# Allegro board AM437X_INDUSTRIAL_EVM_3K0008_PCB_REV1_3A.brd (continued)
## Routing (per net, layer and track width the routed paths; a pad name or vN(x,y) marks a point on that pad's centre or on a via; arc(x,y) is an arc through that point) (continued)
SPI0_DIN: length 106.3
  TOP w0.13: v1(84.53,80.85) 84.53,78.71 83.43,77.61 83.43,73.55 83.2,73.32 82.75,73.32 U11.T22
  L4_SIG2 w0.13: J16.26 102.37,4.82 102.37,6.61 105.95,10.2 106.62,10.2 107.21,10.78 107.21,14.68 107.61,15.08 107.61,20.92 108.65,21.96 108.65,24.44 108.65,24.44 108.65,24.95 109.76,26.06 109.76,29.87 107.78,31.85 107.78,35.98 107.47,36.29 107.47,39.61 108.47,40.61 108.47,44.41 109.66,45.6 109.66,48.3 108.75,49.22 108.75,52.8 105.26,56.28 103.58,56.28 101.62,58.25 101.62,59.62 101.3,59.94 97.19,64.04 97.19,64.88 96.76,65.32 94.99,67.08 94.99,72.81 92.37,75.43 92.37,78.55 90.71,80.21 85.64,80.21 85,80.85 v1(84.53,80.85)
SPI0_SCLK: length 103.4
  L4_SIG2 w0.13: J16.24 106.37,4.86 106.37,6.29 109.35,9.27 109.35,11.48 108.75,12.08 108.75,14.04 109.15,14.44 109.15,20.28 110.19,21.32 110.19,24.31 110.59,24.71 111.3,25.42 111.3,29.88 111.3,36.03 111.01,36.33 111.01,38.38 111.83,39.19 111.83,45.02 111.35,45.49 111.35,48.79 110.36,49.79 110.36,53.55 107.7,56.21 107.7,58.61 107.44,58.87 106.96,58.87 102.99,62.84 102.22,63.61 99.81,63.61 98.73,64.68 98.73,66.64 97.72,67.66 97.72,68.98 96.71,69.99 96.71,75.54 91.79,80.46 91.79,80.47 91.43,80.83 87.83,80.83 86.49,82.17 84.36,82.17 84.02,81.82 83.62,81.82 82.3,83.15 v1(82.3,84.84)
  BOTTOM w0.13: v1(82.3,84.84) 82.3,84.2 R385.2
SPIMEM_CLK: length 40.9
  TOP w0.13: R128.1 63.34,67.15 60.11,67.15 59.56,67.69 57.58,67.69 56.94,67.06 56.24,67.06 55.68,67.62 47.42,67.62 46.15,68.89 43.81,68.89 43.59,69.11 43.59,69.41 43.74,69.56 45.21,69.56 45.38,69.73 45.38,70.01 45,70.38 45,70.39 44.49,70.9 42.96,70.9 42.16,70.1 42.16,68.96 v1(42.93,68.2)
  BOTTOM w0.13: U46.16 44.45,60.83 43.43,61.85 43.43,67.69 v1(42.93,68.2)
SPIMEM_CS: length 35.3
  TOP w0.13: v1(41.53,68.83) 45.3,65.06 46.95,65.06 49.53,62.48 49.53,62.46 50.04,61.96 50.5,61.96 50.65,62.11 50.65,62.28 50.8,62.43 51.02,62.43 51.17,62.28 51.17,62.11 51.32,61.96 51.54,61.96 51.69,62.11 51.69,62.28 51.85,62.43 52.06,62.43 52.21,62.28 52.21,62.11 52.37,61.96 52.58,61.96 52.73,62.11 52.73,62.28 52.89,62.43 53.1,62.43 53.26,62.28 53.26,62.11 53.41,61.96 53.62,61.96 53.78,62.11 53.78,62.28 53.93,62.43 54.15,62.43 54.3,62.28 54.3,62.11 54.45,61.96 55.39,61.96 55.54,62.11 55.54,62.74 55.7,62.89 55.91,62.89 56.06,62.74 56.06,62.11 56.22,61.96 56.43,61.96 56.59,62.11 56.59,62.74 56.74,62.89 56.95,62.89 57.11,62.74 57.11,62.11 57.26,61.96 57.42,61.96 58.6,63.14 60.2,63.14 60.73,62.61 61.85,62.61 62.86,61.59 R144.1
  BOTTOM w0.13: v1(41.53,68.83) 41.15,68.45 U46.7
SPIMEM_D0: length 31.8
  TOP w0.13: v1(44.58,66.82) 46.13,66.82 46.66,66.29 48.62,66.29 49.28,65.63 49.96,65.63 50.6,66.27 54.76,66.27 55.47,65.56 55.47,64.28 55.86,63.88 56.03,63.88 56.19,64.03 56.19,64.55 56.34,64.7 56.55,64.7 56.71,64.55 56.71,64.03 56.86,63.88 57.66,63.88 58.17,64.39 R137.1
  BOTTOM w0.13: v1(44.58,66.82) 44.23,66.47 44.23,66.13 44.38,65.98 45.08,65.98 45.23,65.83 45.23,65.61 45.08,65.46 44.38,65.46 44.23,65.3 44.23,65.09 44.38,64.94 45.08,64.94 45.23,64.78 45.23,64.57 45.08,64.41 44.38,64.41 44.23,64.26 44.23,64.05 44.38,63.89 45.08,63.89 45.23,63.74 45.23,63.52 45.08,63.37 44.38,63.37 44.23,63.22 44.23,62.87 44.99,62.1 U46.15
SPIMEM_D1: length 29.5
  TOP w0.13: v1(42.93,70.1) 42.93,68.96 43.43,68.45 45.97,68.45 47.24,67.18 55.5,67.18 56.06,66.62 57.12,66.62 57.76,67.26 59.36,67.26 59.94,66.67 v1(61.34,66.67)
  BOTTOM w0.13: R449.1 v1(61.34,66.67) ; v1(42.93,70.1) 41.21,70.1 41.05,69.95 41.05,69.62 40.9,69.47 40.69,69.47 40.53,69.62 40.53,69.95 40.38,70.1 39.75,70.1 39.37,69.72 U46.8
SPIMEM_D2: length 28.6
  TOP w0.13: v1(58.93,63.63) 58.04,63.63 57.78,63.37 55.35,63.37 54.89,62.92 49.71,62.92 48.82,63.81 48.82,65.48 48.46,65.84 46.18,65.84 v1(45.72,66.29)
  BOTTOM w0.13: v1(45.72,66.29) 45.09,66.93 45.09,68.49 44.88,68.69 44.28,68.69 44.12,68.86 44.12,69.5 44.34,69.72 U46.9 ; R457.1 59.94,64.39 59.25,64.39 58.93,64.06 v1(58.93,63.63)
SPIMEM_D3: length 34.6
  TOP w0.13: v1(44.45,67.82) 45.01,67.25 46.44,67.25 46.94,66.75 55.32,66.75 55.9,66.17 55.9,65.81 56.25,65.46 60.13,65.46 60.2,65.53 v1(60.32,65.53)
  BOTTOM w0.13: v1(60.32,65.53) 60.5,65.53 60.86,65.18 61.38,65.18 61.58,65.38 61.9,65.38 62.1,65.18 62.42,65.18 62.78,65.53 R453.1 ; U46.1 39.01,60.83 39.28,60.56 40.37,60.56 41.06,61.25 41.06,62.17 42.45,63.57 42.45,68.39 42.73,68.67 43.6,68.67 v1(44.45,67.82)
SYNCI: length 96
  TOP w0.13: v1(111.25,10.16) R257.1 ; v1(82.8,80.7) 82.8,78.99 82.04,78.23 82.04,75.72 81.48,75.16 81.48,74.61 U11.R24
  L4_SIG2 w0.13: v1(106.43,13.72) 105.76,13.72 105.3,14.17 105.3,18.87 106.12,19.68 106.12,21.53 107.16,22.58 107.16,23.82 107.16,25.57 108.27,26.68 108.27,29.18 106.29,31.16 106.29,35.3 105.98,35.61 105.98,36.97 105.98,40.23 106.33,40.57 106.33,44.16 105.48,45.01 105.48,49.95 102.22,53.21 101.06,54.37 101.06,56.54 100.13,57.48 100.13,59.01 99.81,59.32 95.71,63.43 95.71,64.27 93.51,66.47 93.51,70.78 90.04,74.24 90.04,75.22 88.35,76.92 88.35,77.64 87.12,78.87 83.82,78.87 82.8,79.88 v1(82.8,80.7)
  BOTTOM w0.13: v1(111.25,10.16) 107.7,13.72 v1(106.43,13.72)
SYS_RESETN: length 386.6
  TOP w0.13: R152.2 v1(37.08,57.15) ; v1(15.49,73.79) 19.3,77.6 v1(22.23,77.6) ; v1(45.69,116.05) 46.48,116.84 48,116.84 48,116.84 54.11,116.84 54.93,116.01 58.08,116.01 58.09,116.02 59.33,116.02 61.97,118.66 136.1,118.66 138.3,116.46 138.3,98.76 133.01,93.46 133.01,83.78 v1(133.48,83.31)
  L3_SIG1 w0.13: v1(129.29,36.58) 130.3,37.59 130.3,45.47 134.87,50.04 134.87,50.93 135.64,51.69 v1(135.64,52.45) ; v1(24.89,105.41) 24.97,105.41 27.82,108.26 31.38,108.26 34.85,111.73 34.85,116.79 36.69,118.63 43.35,118.63 44.83,117.15 44.83,116.92 v1(45.69,116.05) ; v1(133.48,83.31) 134.75,82.04 v1(134.75,73.53)
  L4_SIG2 w0.13: v1(135.64,52.45) 135.64,69.41 134.75,70.3 v1(134.75,73.53) ; v1(37.08,57.15) 37.74,57.81 37.74,58.9 36.37,60.27 33.6,60.27 29.88,56.55 19.16,56.55 17.87,57.84 17.87,58.31 18.41,58.86 18.41,70.87 v1(15.49,73.79) 15.49,74.36 13.91,75.95 13.91,86.17 14.59,86.85 14.59,101.71 16.51,103.63 18.34,103.63 20.31,105.6 23.73,105.6 23.92,105.41 v1(24.89,105.41)
  BOTTOM w0.13: U43.2 v1(22.23,77.6) 26.8,77.6 28.19,78.99 28.19,83.57 28.56,83.94 30.1,83.94 30.47,83.57 30.47,83.05 30.35,82.94 U42.2 ; R389.2 v1(133.48,83.31) ; J16.25 104.33,4.86 104.33,3.32 105.01,2.63 123.72,2.63 124.37,3.29 124.37,7.48 125.35,8.46 125.35,11.38 122.63,14.1 122.63,28.22 129.29,34.87 v1(129.29,36.58) R499.1 ; U44.2 v1(15.49,73.79)
SYS_WARMRESETN: length 153.2
  TOP w0.13: R86.2 75.56,84.58 v1(75.56,86.87) 76.07,86.87 R69.1
  L3_SIG1 w0.13: v1(135.5,73.15) 135.5,73.53 135.5,73.54 135.5,84.84 134.34,86 134.34,86.84 134.09,87.08 134.09,87.95 135.01,88.87 135.01,95.56 135.72,96.27 135.72,98.03 131.21,102.54 129.51,102.54 127.14,104.91 111.57,104.91 111,105.48 107.78,105.48 106.81,104.51 101.18,104.51 98.09,101.42 94.56,101.42 91.8,98.65 83.21,98.65 79.61,95.06 79.61,92.05 76.53,88.97 76.09,88.97 75.56,88.44 v1(75.56,86.87) ; v1(136.14,51.31) 136.14,48.01 135.14,47 v1(135.14,41.42) 133.99,40.26 v1(131.95,40.26)
  L4_SIG2 w0.13: v1(135.5,73.15) 135.5,73.14 135.06,72.7 135.06,70.42 136.02,69.46 136.02,53 136.14,52.87 v1(136.14,51.31)
  BOTTOM w0.13: U54.4 v1(135.14,41.42) ; R499.2 R498.1 C287.1 v1(131.95,40.26) 129.03,40.26 127.64,41.66 R489.1
SYSBOOT0: length 22
  TOP w0.13: R26.1 v1(62.1,98.37) 62.1,97.54 61.72,97.16 61.72,94.63 59.85,92.76 59.85,85.67 60.03,85.5 60.03,82.03 59.32,81.32 U9.17
  BOTTOM w0.13: R26.1 v1(62.1,98.37)
SYSBOOT1: length 20.1
  TOP w0.13: U9.15 59.22,82.62 59.72,83.12 59.72,85.37 59.54,85.54 59.54,93.58 60.45,94.49 60.45,98.04 60.71,98.3 v1(60.71,98.37) R25.1
  BOTTOM w0.13: R25.1 v1(60.71,98.37)
SYSBOOT2: length 18.3
  TOP w0.13: U9.13 59.05,83.92 59.4,84.27 59.4,85.25 59.24,85.42 59.24,94.31 58.93,94.61 58.93,97.92 59.31,98.3 v1(59.31,98.35) R24.1
  BOTTOM w0.13: R24.1 v1(59.31,98.35)
SYSBOOT3: length 16.6
  TOP w0.13: R23.1 57.91,98.48 v1(57.64,98.22) 57.66,98.2 57.66,93.6 58.93,92.33 58.93,86.44 57.71,85.22 U9.11
  BOTTOM w0.13: R23.1 57.91,98.48 v1(57.64,98.22)
SYSBOOT4: length 20.8
  TOP w0.13: R30.1 v1(67.69,98.35) ; v1(64.16,83.92) U9.8
  L3_SIG1 w0.13: v1(64.16,83.92) 64.88,84.64 64.88,85.48 64.6,85.76 64.36,86 63.95,86 62.79,87.16 62.79,92.8 66.43,96.44 66.43,97.36 67.17,98.09 67.44,98.09 v1(67.69,98.35)
  BOTTOM w0.13: R30.1 v1(67.69,98.35)
SYSBOOT5: length 23.4
  TOP w0.13: U9.6 61.52,82.62 60.95,83.2 60.95,85.88 60.78,86.06 60.78,92.38 61.72,93.32 65.38,93.32 66.29,94.24 v1(66.29,98.37) R29.1
  BOTTOM w0.13: R29.1 v1(66.29,98.37)
SYSBOOT6: length 23.4
  TOP w0.13: U9.4 61.68,81.32 60.64,82.36 60.64,85.75 60.47,85.93 60.47,92.5 61.59,93.63 63.62,93.63 64.9,94.91 v1(64.9,98.37) R28.1
  BOTTOM w0.13: R28.1 v1(64.9,98.37)
SYSBOOT7: length 23.8
  TOP w0.13: R27.1 v1(63.5,98.37) 63.5,97.54 63.12,97.16 63.12,94.53 62.53,93.94 61.46,93.94 60.16,92.63 60.16,85.8 60.33,85.63 60.33,81.34 61.66,80.02 U9.2
  BOTTOM w0.13: R27.1 v1(63.5,98.37)
SYSBOOT8: length 10.9
  TOP w0.13: R39.1 v1(62.48,94.49)
  BOTTOM w0.13: U39.17 61.97,88.81 61.92,88.86 60.87,88.86 60.45,89.28 60.45,93.29 61.65,94.49 v1(62.48,94.49) R39.1
SYSBOOT9: length 9.5
  TOP w0.13: R40.1 v1(63.88,94.49)
  BOTTOM w0.13: U39.15 61.9,90.11 60.94,91.07 60.94,92.95 61.85,93.85 63.25,93.85 v1(63.88,94.49) R40.1
SYSBOOT10: length 9.3
  TOP w0.13: R41.1 v1(65.53,94.49)
  BOTTOM w0.13: U39.13 61.53,91.41 61.25,91.69 61.25,92.3 62.08,93.13 63.56,93.13 64.91,94.49 v1(65.53,94.49) R41.1
SYSBOOT11: length 6.3
  TOP w0.13: R42.1 v1(66.93,94.49)
  BOTTOM w0.13: U39.11 63.58,92.71 64.78,93.92 66.36,93.92 v1(66.93,94.49) R42.1
SYSBOOT12: length 7.5
  TOP w0.13: R35.1 v1(56.9,94.49)
  BOTTOM w0.13: R35.1 v1(56.9,94.49) 56.9,93.85 57.39,93.36 58.16,93.36 58.89,92.62 58.89,91.87 58.44,91.41 U39.8
SYSBOOT13: length 7.8
  TOP w0.13: R36.1 v1(58.29,94.49)
  BOTTOM w0.13: U39.6 58.11,90.11 59.2,91.2 59.2,92.95 58.29,93.85 v1(58.29,94.49) R36.1
SYSBOOT14: length 9.3
  TOP w0.13: R37.1 v1(59.69,94.49)
  BOTTOM w0.13: R37.1 v1(59.69,94.49) 59.69,93.85 59.51,93.67 59.51,89.48 58.84,88.81 U39.4
SYSBOOT15: length 11.1
  TOP w0.13: R38.1 v1(61.09,94.59)
  BOTTOM w0.13: U39.2 58.81,87.51 59.82,88.52 59.82,93.32 v1(61.09,94.59) R38.1
TCK: length 3
  TOP w0.13: J7.11 v1(137.67,80.77)
  BOTTOM w0.13: v1(137.67,80.77) R407.1
UARTX_RXD: length 51.2
  TOP w0.13: R89.2 80.67,84.1 80.67,85.06 80.38,85.35 v1(80.38,86.61) ; U13.38 112.35,62.21 113.03,62.89 113.03,63.88 v1(112.67,64.24)
  L4_SIG2 w0.13: v1(80.38,86.61) 80.82,87.05 81.74,87.05 82.52,87.83 84.13,87.83 86.28,85.68 86.56,85.68 86.96,85.28 91.2,85.28 96.05,80.42 96.69,80.42 98.51,78.59 99.55,78.59 100.2,77.94 100.2,75.15 100.75,74.6 100.75,73.29 104.81,69.23 104.81,68.73 105.32,68.22 106.73,68.22 108.41,66.55 110.25,66.55 112.56,64.24 v1(112.67,64.24)
UARTX_TXD: length 54.6
  TOP w0.13: v1(109.22,69.72) 109.22,65.76 108.81,65.35 108.81,62.46 109.56,61.71 U13.39 ; R88.2 79.2,84.53 79.2,85.49 78.74,85.95 v1(78.74,86.61)
  L4_SIG2 w0.13: v1(109.22,69.72) 108.53,70.41 105.37,70.41 100.51,75.28 100.51,78.07 99.68,78.9 98.64,78.9 96.81,80.73 96.18,80.73 93.28,83.63 93.28,85.07 92.5,85.85 91.06,85.85 90.42,86.49 87.76,86.49 87.51,86.73 86.11,86.73 84.71,88.14 82.39,88.14 81.61,87.36 79.48,87.36 v1(78.74,86.61)
USBJTAG_ENN: length 54.4
  L4_SIG2 w0.13: v1(134.49,48.13) 134.68,48.32 134.68,50.2 133.86,51.03 133.86,53.21 134.73,54.08 134.73,58.4 133.48,59.65 133.48,63.3 130.81,65.96 130.81,68.45 129.16,70.1 v1(128.37,70.1)
  BOTTOM w0.13: U45.14 127.72,75.48 R421.2 ; U45.15 v1(128.37,70.1) 129.18,70.1 129.63,70.55 130.74,70.55 132.97,72.77 132.97,76.07 131.83,77.22 131.83,80.26 132.91,81.35 132.91,82.36 131.92,83.35 U41.4 ; v1(134.49,48.13) 133.06,49.57 U49.4
VADD33_PRUETH0: length 3.4
  TOP w0.305: U7.14 24.11,90.53 23.88,90.3 23.37,90.3 23.24,90.42 C33.1
  TOP w0.508: C33.1 v3(22.61,89.67)
VADD33_PRUETH1: length 3.4
  TOP w0.305: C58.1 23.24,65.15 23.37,65.02 23.88,65.02 24.11,65.26 U12.14
  TOP w0.508: C58.1 v3(22.61,64.4)
VAM437X_DDR_VREF: length 0.5
  TOP w0.13: U11.T6 82.48,62.6 v1(82.81,62.93)
VENDAT: length 7
  BOTTOM w0.508: 10.8,38.02 J10.8 ; J10.8 10.8,39.66 ; J10.8 12.44,39.66 ; J10.8 12.44,38.02 ; 13.02,35.33 J10.2 11.37,35.33
VETH1_AVDDH: length 7.3
  BOTTOM w0.254: v3(39.88,97.16) 40.43,96.6 U37.1 ; v3(38.86,95.25) 39.15,94.96 U37.47 ; U37.12 45.93,96.48 46.35,96.9 C142.1
  BOTTOM w0.508: v3(39.48,78.99) C182.1 v3(40.64,80.26) ; C142.1 v3(47.12,97.92)
  vias: v3(36.32,72.77) v3(39.62,72.39) v3(40.26,71.5) v3(40.89,72.39)
VETH1_AVDDL: length 9
  TOP w0.508: v3(52.47,99.69) FB2.2 v3(51.45,98.68) ; v3(51.18,99.95) 50.53,99.95 C21.1 v3(50.02,100.71)
  BOTTOM w0.254: U37.4 41.93,97.06 41.68,97.31 v3(41.68,97.74) ; U37.9 44.43,97.01 44.83,97.41 C143.1
  BOTTOM w0.508: C143.1 v3(44.07,97.92)
VETH1_AVDDL_PLL: length 8.2
  TOP w0.508: v3(52.47,95.63) FB3.2 v3(51.43,96.65) ; C26.1 v3(37.85,93.98) ; v3(35.69,95.65) C22.1 37.32,96.01 v3(38.23,96.01)
  BOTTOM w0.254: C26.1 37.86,93.22 38.1,93.46 U37.44
  BOTTOM w0.508: C26.1 v3(37.85,93.98)
VETH1_AVDDL_PMOS: length 6.1
  TOP w0.508: v3(54.47,94.87) FB4.1 v3(54.47,92.84) ; v3(55.5,98.68) FB2.1 v3(54.47,97.66) ; v3(54.47,95.63) FB3.1 v3(55.5,96.65)
  vias: v3(33.78,76.33) v3(33.78,75.06) v3(35.05,76.33) v3(35.05,75.06)
VETH1_DVDDH: length 33.8
  TOP w0.508: v3(37.34,81.67) 37.21,81.55 37.21,79.88 34.81,77.48 v3(29.72,77.48) ; R66.2 v3(37.59,87.76)
  BOTTOM w0.254: v3(37.34,91.19) 37.61,91.46 U37.40 ; v3(41.02,88.01) 41.43,88.42 U37.34 ; C149.1 48.77,94.61 48.11,93.96 U37.16
  BOTTOM w0.381: v3(29.72,77.48) C187.1 29.72,80.13 U42.5
  BOTTOM w0.508: v3(34.52,82.91) 33.82,82.91 R401.1 34.13,83.79 v3(34.59,83.79) ; R336.1 v3(51.18,95.63) ; v3(41.91,81.67) R396.1 R395.1 ; R345.1 v3(51.18,92.84) ; v3(37.34,81.67) R400.1 R399.1 ; v3(46.48,81.67) R392.1 R393.1 ; D20.1 v3(33.27,85.34) ; 31.12,85.72 v3(32,85.72) ; v3(49.17,93.83) 49.28,93.93 C149.1 ; R353.2 v3(36.58,90.42)
VETH1_DVDDL: length 16.9
  L3_SIG1 w0.508: v3(43.81,87.88) 42.16,89.53 39.37,89.53 v3(38.23,90.68)
  BOTTOM w0.254: U37.23 49.24,90.46 C162.1 ; U37.30 43.43,88.27 v3(43.81,87.88) ; U37.39 38.56,90.96 38.28,90.68 v3(38.23,90.68) ; v3(47.57,92.85) 47.47,92.96 U37.18 ; U37.14 v3(47.75,94.96) ; v3(45.97,87.88) 45.43,88.43 U37.26
  BOTTOM w0.508: C162.1 v3(49.28,89.66)
VMTR_PWRIN: length 4.6
  TOP w0.508: 3.39,17.53 J14.1 ; J14.1 3.39,19.14 ; J14.1 5,19.14 ; J14.1 5,17.53
VPWRIN_JCK: length 13.7
  TOP w0.508: J12.1 127.14,21.25 ; J12.1 127.14,24.47 ; J12.1 123.91,21.25 ; J12.1 123.91,24.47 ; 135.19,19.64 J13.1 ; J13.1 136.81,19.64 ; J13.1 136.81,21.25 ; J13.1 135.19,21.25
VUSB_FTDI: length 27.4
  TOP w0.254: R168.2 v1(114.18,51.69)
  TOP w0.508: D12.2 132.27,67.1 v1(131.47,67.89)
  L4_SIG2 w0.508: v3(127.89,62) 128.14,62.26 128.14,63.37 128.83,64.06 128.83,66.28 v3(130.24,67.69)
  BOTTOM w0.508: v1(114.18,51.69) 114.89,52.4 116.79,52.4 122.55,58.17 122.55,59.31 125.25,62 v3(127.89,62)
VUSB_JTAG: length 4.9
  TOP w0.508: v3(133.6,64.39) 133.6,62.23 132.46,61.09 v3(132.45,61.09)
  BOTTOM w0.305: U47.1 v3(132.45,61.09)
XTIN: length 13.2
  TOP w0.13: U13.2 124.53,57.71 125.86,56.39 v1(130.3,56.39)
  BOTTOM w0.13: v1(130.3,56.39) 130.05,56.13 130.05,55.5 129.79,55.24 C261.1 128.02,55.24 126.73,53.96 Y4.1
XTOUT: length 12.2
  TOP w0.13: U13.3 125.18,58.21 126.24,57.15 v1(130.18,57.15)
  BOTTOM w0.13: v1(130.18,57.15) 129.67,56.64 C255.1 128.02,56.64 126.6,58.06 Y4.2
N10692191: length 9.3
  TOP w0.13: SW2.3 SW2.4 131.14,37.72 v1(129.29,37.72)
  BOTTOM w0.13: R498.2 v1(129.29,37.72)
N11217419: length 2
  BOTTOM w0.13: R508.1 R507.1 C306.1
N11219802: length 1.5
  TOP w0.305: R232.1 93.35,11.82 U25.7
N11219922: length 1.5
  TOP w0.305: R233.1 93.98,11.48 94.35,11.85 U25.9
N11219986: length 2.9
  TOP w0.254: U25.5 92.75,15.75 C108.1 R225.1
N11220684: length 2.7
  TOP w0.254: C109.1 96.55,15.85 U25.1
  BOTTOM w0.508: R549.2 96.77,16.13 v1(97.03,16.38)
N11290828: length 8.8
  TOP w0.13: R87.1 76.95,82.92 76.95,81.92 76.67,81.64 76.67,78.6 77.22,78.05 77.22,77.52 76.94,77.24 76.94,75.81 76.59,75.46 U11.G25
N11290910: length 11.1
  TOP w0.13: U11.G22 76.34,73 76.24,73.1 76.24,73.52 76.24,73.52 76.24,75.44 76.71,75.91 76.71,76.61 76.17,77.14 76.17,81.44 75.69,81.93 75.69,82.68 R86.1
N11291034: length 10.7
  TOP w0.13: R90.1 85.6,81.25 84.78,80.44 84.78,78.56 84.04,77.82 84.04,74.21 84.26,73.99 84.69,73.99 U11.Y23
N12081710: length 23.5
  BOTTOM w0.13: J8.1 30.86,77.6 32.79,77.6 34.54,79.35 34.54,80.23 36.48,82.16 36.48,84.3 36.63,84.45 36.63,86.62 35.81,87.43 35.81,88.66 36.32,89.16 37.06,89.16 37.56,89.66 R353.1 38.23,89.66 39.03,90.46 U37.38
N12123192: length 7
  BOTTOM w0.13: R270.2 33.77,115.56 J4.11
N12123204: length 7.3
  BOTTOM w0.13: J4.14 41.41,116.08 38.23,116.08 R269.2
N12138943: length 2.2
  TOP w0.13: v1(39.12,96.52) 39.12,96.9 R32.1
  BOTTOM w0.13: U37.48 39.71,95.93 v1(39.12,96.52)
N12139138: length 10.4
  BOTTOM w0.13: TP18.1 35.94,86.87 35.43,87.38 35.43,89.99 35.87,90.42 35.87,90.81 36.88,91.82 38.61,91.82 38.75,91.96 U37.41
N12220066: length 11.7
  TOP w0.305: U7.24 29.94,88.81 v3(31.12,87.63) C38.1 ; U7.13 v1(23.88,91.03) ; v1(23.46,88.67) 23.49,88.7 23.49,89.15 24.37,90.03 U7.15
  BOTTOM w0.508: v1(23.88,91.03) 24.64,90.27 C163.1 C164.1 ; v1(23.46,88.67) 23.3,88.5 C167.1 v3(20.95,88.5)
N12225140: length 4.4
  BOTTOM w0.13: J9.11 4.32,73.93 R420.1
N12225158: length 11.8
  TOP w0.305: U12.15 24.37,64.76 23.51,63.89 v1(23.51,63.25) ; U12.13 v1(23.88,65.76) ; C65.1 v3(31.12,62.23) 29.81,63.53 U12.24
  BOTTOM w0.508: C237.1 C232.1 24.64,65 v1(23.88,65.76) ; v3(20.9,63.23) C244.1 23.49,63.23 v1(23.51,63.25)
N12225278: length 44.1
  TOP w0.13: v1(35.69,66.27) 34.54,66.27 33.93,65.66 R134.1 ; J9.10 5.1,57.66 11.97,57.66 13.04,58.74 16.29,58.74 16.99,58.04 v1(18.34,58.04)
  L4_SIG2 w0.13: v1(18.34,58.04) 18.88,57.49 30.32,57.49 33.63,60.81 33.63,65.91 33.99,66.27 v1(35.69,66.27)
N12225708: length 9.9
  TOP w0.13: v1(66.04,57.15) 68.83,59.94 69.4,59.94 70.39,60.92 72.3,60.92 72.57,60.65 U11.A3
  BOTTOM w0.13: R473.2 65.53,56.64 v1(66.04,57.15)
N12225872: length 9.8
  TOP w0.13: U11.E24 75.63,74.64 75.63,75.16 76.43,75.96 76.43,76.56 75.84,77.14 75.84,81.34 75.06,82.13 R85.2
N12226470: length 4.1
  BOTTOM w0.13: R475.1 4.45,60.35 J9.9
N12226600: length 1.5
  BOTTOM w0.13: U44.1 17.59,74.74 R431.1
N12591797: length 62.7
  TOP w0.13: U11.H20 77.29,71.7 v1(77.69,71.31)
  BOTTOM w0.13: v1(77.69,71.31) 76.23,72.77 76.23,75.7 76.42,75.9 76.42,77.39 73.64,80.17 73.64,82.02 74.3,82.68 74.3,83.8 73.66,84.44 73.66,85.69 69.05,90.3 67.31,90.3 66.58,89.57 66.58,84.12 65.44,82.99 63.96,82.99 62.5,84.44 62.5,84.89 61.82,85.58 59.82,85.58 59.59,85.81 58.3,85.81 58.1,85.62 55.35,85.62 52.91,88.05 52.91,92.99 53.47,93.54 53.47,99.44 TP2.1
N12595082: length 17.1
  TOP w0.13: R162.2 100,53.09 98.6,54.49 98.6,54.97 93.26,60.3 91.22,60.3 91.18,60.34 87.29,60.34 U11.AC3
N12745256: length 3.6
  TOP w0.13: v1(9.65,112.52) 9.65,112.39 R10.1 R9.2
  BOTTOM w0.13: Q8.G 9.45,112.19 9.65,112.39 v1(9.65,112.52)
N12745282: length 3.2
  BOTTOM w0.13: R272.1 8.99,114.81 8.51,114.33 Q8.D
N12745290: length 2.5
  TOP w0.13: U1.2 v1(9.08,115.76)
  BOTTOM w0.13: v1(9.08,115.76) 9.15,115.82 R272.2
N12745520: length 3.5
  TOP w0.13: v1(16.28,112.37) 15.85,112.37 R8.2 R7.2
  BOTTOM w0.13: Q6.G 16.18,112.27 v1(16.28,112.37)
N12745536: length 5.3
  BOTTOM w0.13: R268.1 15.6,117.22 15.8,117.02 15.8,114.88 15.24,114.33 Q6.D
N12745804: length 3.2
  TOP w0.13: v1(12.95,112.39) R12.2 R11.2
  BOTTOM w0.13: v1(12.95,112.39) 12.88,112.32 Q7.G
N12745812: length 2.6
  TOP w0.13: v1(15.19,115.82) 13.88,115.82 U1.4
  BOTTOM w0.13: R271.2 v1(15.19,115.82)
N12745820: length 3.5
  BOTTOM w0.13: R271.1 12.22,114.81 11.94,114.53 Q7.D
N12825337: length 16.2
  L4_SIG2 w0.13: J10.7 19.96,46.63 23.32,46.63 24,47.32 v1(24,48.26)
  BOTTOM w0.13: v1(24,48.26) U55.6
N12825341: length 19.1
  L4_SIG2 w0.13: v1(24,49.28) 19.51,49.28 J10.6
  BOTTOM w0.13: U55.7 25.27,48.01 v1(24,49.28)
N12825345: length 1.8
  BOTTOM w0.13: U55.4 21.01,40.83 R493.1
N12825349: length 8.2
  BOTTOM w0.13: U55.1 26.54,41.66 31.5,46.61 TP12.1
N12825453: length 13
  BOTTOM w0.13: J10.4 7.11,36.88 R512.1 7.11,28.96 6.35,28.19 U57.7
N12825465: length 12.7
  BOTTOM w0.13: J10.3 8.13,34.81 R512.2 8.13,28.7 6.35,26.92 U57.6
N12825469: length 4.5
  BOTTOM w0.13: U57.1 13.71,29.46 R514.1
N12825473: length 4.8
  BOTTOM w0.13: R540.1 13.34,24.38 12.07,25.65 U57.4
N12825749: length 4.5
  BOTTOM w0.13: R526.1 12.62,26.29 11.98,26.92 U57.3
N12957779: length 2.4
  TOP w0.13: U13.28 115.48,69.06 R114.2
N12957783: length 36.2
  TOP w0.13: v1(115.82,71.55) 115.45,71.18 R114.1
  L4_SIG2 w0.13: v1(129.92,49.4) 129.03,50.3 129.03,58.78 125.36,62.45 125.36,63.18 125.86,63.68 125.86,68.81 124.82,69.85 122.32,69.85 120.62,71.55 v1(115.82,71.55)
  BOTTOM w0.13: U49.6 130.48,49.97 v1(129.92,49.4)
N12957791: length 2.9
  TOP w0.13: U13.32 113.48,67.25 112.78,67.95 112.78,68.71 R112.2
N12957851: length 5.4
  TOP w0.13: R168.1 R169.2 R170.2 118.48,53.96 U13.59
N12957949: length 31.6
  TOP w0.13: v1(117.86,72.03) 115.06,72.03 114.43,71.41 R113.1
  L4_SIG2 w0.13: v1(117.86,72.03) 119.23,72.03 119.76,72.57 119.76,74.93 122.68,77.85 122.68,81.41 123.44,82.17 124.71,82.17 124.97,81.91 128.65,81.91 129.48,82.74 132.59,82.74 133.03,82.3 v1(133.48,82.3)
  BOTTOM w0.13: U41.3 132.03,83.75 v1(133.48,82.3)
N12958009: length 3.9
  TOP w0.13: U13.14 123.95,63.71 124.08,63.59 124.54,63.59 125.73,64.77 R135.1
N12958129: length 23.9
  TOP w0.13: v1(120.5,51.82) 119.99,51.31 118.63,51.31 R171.2 ; v1(131.44,61.14) 131.95,61.65 131.95,62.89 132.27,63.21 D12.1
  BOTTOM w0.13: v1(120.5,51.82) 121.18,52.5 121.18,55.52 123.32,57.66 123.32,59.08 125.37,61.14 v1(131.44,61.14)
N12958219: length 4
  TOP w0.13: R178.1 R180.2 U16.4
N12958339: length 9.5
  TOP w0.13: TP10.1 110.24,65.48 109.47,64.72 109.47,63.88 110.14,63.21 U13.36
N12958347: length 2.9
  TOP w0.13: R171.1 118.98,53.44 U13.60
N12958931: length 25.8
  TOP w0.13: R116.1 117.48,70.97 v1(119.15,72.64)
  L4_SIG2 w0.13: v1(132.46,84.07) 127.64,84.07 126.62,83.06 125.22,83.06 124.71,82.55 123.19,82.55 122.3,81.66 122.3,78.23 119.15,75.08 v1(119.15,72.64)
  BOTTOM w0.13: U41.2 132.39,84.15 v1(132.46,84.07)
N12958935: length 11.1
  TOP w0.13: v1(120.47,72.09) 118.5,70.11 R117.1
  BOTTOM w0.13: U45.7 125.12,68.27 124.78,68.61 122.94,68.61 120.47,71.07 v1(120.47,72.09)
N12958939: length 12.9
  TOP w0.13: R118.1 121.03,70.61 121.03,72.59 v1(120.52,73.1)
  BOTTOM w0.13: U45.6 125.77,68.31 125.02,69.06 123.27,69.06 120.95,71.37 120.95,72.67 v1(120.52,73.1)
N14606304: length 6.3
  TOP w0.13: U20.L8 76.4,32.08 77.15,32.08 77.19,32.11 77.52,32.11 77.93,32.53 77.93,32.75 78.25,33.06 78.47,33.06 79.43,34.02 79.43,34.6 79.7,34.87 v1(79.7,34.94)
  BOTTOM w0.13: R504.2 80.14,35.37 v1(79.7,34.94)
N14617357: length 7.7
  TOP w0.13: R198.2 100.23,33.56 95.39,33.56 95.19,33.36 95.19,32.87 U21.L8
N14814629: length 11.6
  TOP w0.13: U11.E13 75.29,67.13 v1(74.96,66.81)
  BOTTOM w0.13: v1(74.96,66.81) 74.39,67.38 73.07,67.38 72.6,67.85 68.45,67.85 67.59,68.71 C212.1
N14814645: length 1.5
  TOP w0.13: v1(75.77,68.25) 75.32,67.8 U11.E14
  BOTTOM w0.13: v1(75.77,68.25) 75.56,68.05 C218.1
N14814653: length 13.2
  TOP w0.13: U11.F19 75.93,71.05 75.53,71.45 75.52,71.45 v1(75.46,71.5)
  BOTTOM w0.13: C191.1 65.56,75.56 69.55,71.58 74.02,71.58 74.16,71.43 75.39,71.43 v1(75.46,71.5)
N14814919: length 22.2
  TOP w0.254: U11.W21 83.93,72.35 ; 83.93,72.35 v1(83.9,72.35) ; 83.93,72.35 83.92,72.35 U11.U21
  L3_SIG1 w0.508: v3(88.7,88.57) 86.36,86.23 86.36,82.73 88.01,81.08 88.01,79.6 87.41,78.99 85.22,78.99 84.58,78.36 84.58,73.03 83.9,72.35 v1(83.9,72.35)
  vias: v3(87.27,88.54)
N15803440: length 16
  TOP w0.13: R172.2 98.29,54.37 98.29,54.82 93.11,60 U11.AE2
N15803446: length 10.2
  TOP w0.13: U11.AD6 87.94,62.91 94.73,62.91 95.78,61.85 R143.2
N15803450: length 3
  TOP w0.13: U11.AE4 88.51,61.53 v1(89.71,61.53)
  BOTTOM w0.13: v1(89.71,61.53) 90.39,60.85 R467.1
N15803452: length 5.7
  BOTTOM w0.13: R467.2 91.95,60.83 92.33,60.83 C248.1 93.67,60.91 94.42,60.91 95.51,59.81 Y3.4
N15803458: length 8.7
  TOP w0.13: U11.AE5 90.3,61.95 v1(90.73,61.52)
  BOTTOM w0.13: Y3.1 95.51,62.37 94.36,61.21 93.47,61.21 C243.1 92.46,61.21 91.03,61.21 v1(90.73,61.52)
N15803478: length 9.7
  TOP w0.13: R148.2 96.32,60.83 94.55,62.6 89.96,62.6 89.96,62.6 U11.AE6
N15803480: length 17.7
  TOP w0.13: R163.2 102.01,53.95 100.21,53.95 93.62,60.54 91.32,60.54 91.21,60.65 U11.AE3
N15803482: length 19.4
  TOP w0.13: v1(108.36,59.92) 107.34,60.94 98.4,60.94 R148.1
  BOTTOM w0.13: R479.1 108.09,53.61 ; 108.09,53.61 U48.4 ; 108.09,53.61 108.84,54.36 108.84,57.52 109.22,57.9 109.22,59.05 v1(108.36,59.92)
N15803502: length 14.1
  TOP w0.13: TP13.1 101.6,41.91 101.6,49.53 103.89,51.82 R163.1
N15838226: length 11.3
  TOP w0.203: J5.9 122,105.74
  TOP w0.381: C14.1 122,106.85 122,105.74
  TOP w0.508: C14.1 v1(121.22,106.87)
  BOTTOM w0.508: v1(121.22,106.87) 122.35,106.87 122.54,107.06 125.48,107.06 127.25,105.28 127.25,103.5
N15840029: length 1.8
  BOTTOM w0.508: C125.1 111.12,105.56 U30.4
N15840733: length 1.8
  BOTTOM w0.13: R297.1 133.72,105.92 U31.6
N15910922: length 65.1
  TOP w0.13: R140.2 v1(34.67,63.34) ; v1(74.46,73.82) 74.84,73.82 74.98,73.96 75.62,73.96 U11.F23
  L4_SIG2 w0.13: v1(48.26,70.69) 44.27,70.69 36.92,63.34 v1(34.67,63.34)
  BOTTOM w0.13: v1(48.26,70.69) 48.26,79.5 54.07,85.31 58.22,85.31 58.42,85.5 59.46,85.5 59.69,85.27 61.69,85.27 62.19,84.77 62.19,84.31 63.83,82.68 65.83,82.68 66.67,81.83 66.67,81.22 66.84,81.05 66.84,79.62 67.5,78.95 68.33,78.95 68.39,78.9 69.07,78.9 69.45,79.28 71.88,79.28 73,78.17 73.4,78.17 73.84,77.74 73.84,77.74 74.46,77.12 v1(74.46,73.82)
N15911835: length 2.8
  TOP w0.13: v1(24.38,62.99) 25.08,63.69 U12.16
  BOTTOM w0.13: v1(24.38,62.99) 25.15,62.23 R464.2
N15980233: length 4.3
  TOP w0.13: U23.1 38.19,28.29 37.72,27.81 35.81,27.81 35.43,27.43 C94.1
N15980235: length 3.6
  TOP w0.13: C94.2 37.42,26.92 38.84,28.34 U23.2
N15980277: length 7.8
  TOP w0.13: R214.1 C100.1 R213.2 49.02,26.8 48.26,27.56 46.54,27.56 45.99,28.1 U23.13
N15980287: length 6.3
  TOP w0.13: R186.2 v1(41.91,37.46) 42.67,37.46 44.04,36.09 U23.19
  BOTTOM w0.13: R496.2 v1(41.91,37.46)
N15980309: length 4.7
  TOP w0.13: U23.12 45.34,28.32 46.48,27.18 46.99,27.18 47.62,26.54 R215.2
N15980493: length 1.8
  TOP w0.13: R183.1 36.47,42.42 D15.2
N15980497: length 1.9
  TOP w0.13: R183.2 37.85,44.07 v1(37.59,44.32)
  BOTTOM w0.13: Q10.D v1(37.59,44.32)
N15980559: length 92.6
  TOP w0.13: R83.2 90.55,86.23 90.02,86.77 v1(90.02,89.46) ; v1(47.42,41.53) 46.06,40.17 46.06,39.31 45.09,38.34 45.09,36.29 45.34,36.03 U23.17
  L4_SIG2 w0.13: v1(47.42,41.53) 48.12,42.22 48.12,50.14 47.95,50.3 47.95,54.41 48.57,55.03 48.57,56.31 48.57,56.7 49.53,57.66 49.95,57.66 53.22,60.93 55.26,60.93 55.57,61.24 57.21,61.24 64.26,68.29 64.26,72.06 66.43,74.24 67.31,74.24 68.48,75.4 68.48,77.63 71.29,80.44 72.42,80.44 73.36,81.37 73.36,85.98 75.04,87.67 81.48,87.67 85.83,92.01 89.8,92.01 90.02,91.8 v1(90.02,89.46)
N16086432: length 4.4
  BOTTOM w0.089: 101.95,94.2 101.95,94.04 101.95,93.69 U35.B2
  BOTTOM w0.13: R324.1 103.47,96.61 101.95,95.09 101.95,94.2
N16086456: length 3.4
  BOTTOM w0.13: 101.73,89.03 101.7,89.06 U35.D3
N16086460: length 4.7
  BOTTOM w0.13: 104.14,89.03 104.14,90.04 103.76,90.42 102.87,90.42 102.2,91.1 U35.D2
N16086926: length 3.4
  BOTTOM w0.13: R325.1 102.33,95.98 101.7,95.35 U35.A3
N16086934: length 4.4
  BOTTOM w0.089: 101.95,92.23 101.95,92.69 U35.C2
  BOTTOM w0.13: 101.95,92.23 101.95,90.96 103,89.92 103,89.03
N16087466:
  vias: v3(57.4,114.68) v3(57.4,111.89) v3(58.67,114.68) v3(58.67,111.89) v3(59.94,114.68) v3(59.94,113.16) v3(59.94,111.89)
N16087487: length 3
  TOP w0.13: R18.2 52.7,107.82 U3.3
N16087773: length 3
  TOP w0.13: C17.1 52.58,106.55 U3.4
N16088130: length 3.5
  TOP w0.13: R14.2 U3.6
N16088430: length 5
  TOP w0.13: U3.5 R19.1 v1(62.61,105.82)
  BOTTOM w0.13: R19.1 v1(62.61,105.82)
N16094628: length 4
  TOP w0.13: J7.4 v1(128.4,75.69)
  BOTTOM w0.13: R429.2 v1(128.4,75.69)
N16169613: length 3.7
  BOTTOM w0.13: R546.1 35.69,19.46 36.04,19.81 U58.16
N16169629: length 29.5
  BOTTOM w0.13: U58.18 34.74,20.66 27.27,13.19 23.43,13.19 20.83,10.58 20.83,6.22 19.81,5.21 J15.5
N16169633: length 3.8
  BOTTOM w0.13: R547.1 34.67,19.6 35.39,20.32 U58.17
N16169657: length 22.1
  BOTTOM w0.13: U58.21 32.79,20.27 26.73,14.21 22.8,14.21 21.42,12.83 C347.1 R552.1 J15.2
N16169661: length 23.6
  BOTTOM w0.13: J15.3 R560.1 C351.1 19.32,10.29 22.86,13.83 26.79,13.83 33.44,20.49 U58.20
N16169665: length 26.9
  BOTTOM w0.13: U58.19 34.09,20.45 27.17,13.53 22.99,13.53 20.42,10.95 20.42,8.35 19.81,7.75 C352.1 R565.1 J15.4
N16251668: length 30.6
  TOP w0.13: v1(91.19,97.03) 90.93,97.28 U5.15 ; R97.1 101.15,75.5 101.92,75.5 v1(102.15,75.73)
  L4_SIG2 w0.13: v1(91.19,97.03) 92.71,95.5 94.18,95.5 97.85,91.83 97.85,90.1 99.3,88.65 99.3,87.48 99.52,87.26 99.52,80.29 101.36,78.45 101.36,77.51 102.15,76.71 v1(102.15,75.73)
N16251678: length 35.8
  TOP w0.13: U5.2 v1(90.93,102.36) ; v1(102.73,76.06) 102.73,75.63 102.29,75.19 101.99,75.19 R98.1
  L4_SIG2 w0.13: v1(102.73,76.06) 102.49,76.3 102.49,76.89 101.67,77.71 101.67,78.62 99.85,80.44 99.85,87.37 99.6,87.61 99.6,88.78 98.16,90.23 98.16,91.96 93.19,96.93 93.19,100.1 v1(90.93,102.36)
N16279225: length 42.1
  TOP w0.13: U11.G5 76.59,62.12 76.91,62.45 77.17,62.45 77.21,62.49 v1(77.42,62.49)
  TOP w0.203: U11.F14 U11.F13 75.94,67.13 v1(75.61,66.81)
  TOP w0.254: U11.E17 75.29,70.25 v1(75.28,70.26) ; U11.N21 80.27,72.56 v1(80.05,72.56)
  L3_SIG1 w0.178: 79.27,72.62 79.33,72.57 79.82,72.57 79.82,72.56 v1(80.05,72.56)
  L3_SIG1 w0.254: 79.27,72.62 78.99,72.9 78.99,74.17 78.61,74.55 77.66,74.55 77.18,74.07 77.18,72.43 76.4,71.65 76.32,71.65 75.64,70.97 75.62,70.97 75.34,70.69 75.34,70.67 75.28,70.61 v1(75.28,70.26)
  L4_SIG2 w0.203: 75.6,63.92 77.43,63.92
  L4_SIG2 w0.254: 75.6,63.92 75.31,63.63 74.17,63.63 73.28,64.52 73.28,67.31 ; v1(77.42,62.49) 77.98,63.05 77.98,63.37 77.43,63.92 ; v1(75.28,70.26) 74.37,69.34 73.28,69.34 72.9,68.96 72.9,67.69 73.28,67.31 ; 73.28,67.31 73.29,67.3 75.37,67.3 75.61,67.06 v1(75.61,66.81)
  BOTTOM w0.13: C242.1 67.62,62.99 67.85,63.22 72.43,63.22 72.5,63.16 75.23,63.16 75.3,63.22 75.67,63.22 75.96,62.93 75.96,62.88 76.38,62.45 77.38,62.45 v1(77.42,62.49)
  BOTTOM w0.381: v1(75.28,70.26) 75.28,69.75 C206.1 ; v1(80.05,72.56) 80.73,72.56 C198.1
  vias: v1(68.2,80.52) v1(68.25,79.63)
N16281493: length 9.6
  TOP w0.13: U11.H21 77.43,72.35 v1(77.66,72.13)
  BOTTOM w0.13: TP19.1 76.84,79.38 77.4,78.82 77.4,77.37 77.12,77.08 77.12,72.67 v1(77.66,72.13)
N16283418: length 1.5
  TOP w0.13: C11.1 R14.1
N16286128:
  vias: v3(114.17,75.18) v3(114.17,74.04) v3(114.17,72.77) v3(115.44,75.18) v3(115.44,72.77) v3(116.71,75.18) v3(116.71,72.77)
N16286370: length 3
  TOP w0.13: R94.2 121.41,79.38 U10.3
N16286398: length 3
  TOP w0.13: C44.1 121.54,80.64 U10.4
N16286420: length 2.6
  TOP w0.13: R95.1 U10.6
N16286444: length 4.1
  TOP w0.13: v1(112.39,81.41) R93.1 U10.5
  BOTTOM w0.13: R93.1 v1(112.39,81.41)
N16286506: length 1.3
  TOP w0.13: R95.2 C46.1
N16287061:
  vias: v3(41.02,58.42) v3(41.02,56.01) v3(42.29,58.42) v3(42.29,56.01) v3(43.56,58.42) v3(43.56,57.15) v3(43.56,56.01)
N16287303: length 3
  TOP w0.13: U15.3 36.45,51.82 R175.2
N16287331: length 3
  TOP w0.13: U15.4 36.32,50.55 C77.1
N16287353: length 2.6
  TOP w0.13: R173.2 U15.6
N16287439: length 1.3
  TOP w0.13: R173.1 C75.1
N16288012:
  vias: v3(111.89,37.85) v3(111.89,36.7) v3(111.89,35.43) v3(113.16,37.85) v3(113.16,35.43) v3(114.43,37.85) v3(114.43,35.43)
N16288254: length 3
  TOP w0.13: U17.3 119.13,42.04 R182.2
N16288282: length 3
  TOP w0.13: C79.1 119.25,43.31 U17.4
N16288304: length 2.6
  TOP w0.13: R184.2 U17.6
N16288328: length 4.1
  TOP w0.13: U17.5 R181.2 v1(110.11,44.07)
  BOTTOM w0.13: R181.2 v1(110.11,44.07)
N16288390: length 1.3
  TOP w0.13: R184.1 C82.1
N16700927: length 6.6
  BOTTOM w0.13: R448.1 2.79,68.46 3.16,68.83 3.16,73.05 J9.12
N16702915: length 2.6
  TOP w0.13: v1(115.15,99.44) U6.3
  BOTTOM w0.13: v1(115.15,99.44) 114.68,98.98 R326.1
N16702921: length 7.6
  TOP w0.13: U6.4 v1(114.5,101.7)
  BOTTOM w0.13: R327.1 112.9,99.17 114.5,100.76 v1(114.5,101.7)
N16738182: length 4.1
  TOP w0.13: U15.5 R176.2 v1(45.47,49.78)
  BOTTOM w0.13: R176.2 v1(45.47,49.78)
N16738683: length 4.1
  BOTTOM w0.203: 43.62,47.49 U52.A1 U52.B1 R486.2 43.62,47.49
N16738880: length 2.8
  BOTTOM w0.13: U52.C2 41.27,45.85 R490.1
N16739248: length 4.1
  BOTTOM w0.203: R488.2 111.96,46.36 U53.A1 U53.B1 R488.2
N16739276: length 2.8
  BOTTOM w0.13: U53.C2 114.3,48 R482.1
N16740119: length 4.1
  BOTTOM w0.203: U40.B1 R379.2 114.24,83.7 U40.A1 U40.B1
N16740147: length 3.2
  BOTTOM w0.13: U40.C2 116.59,85.34 R359.1 R360.1
N16740391: length 2.8
  TOP w0.13: R224.1 65.02,15.37 64.34,14.68 U26.1
N16743008: length 2.8
  TOP w0.13: U26.2 63.84,15.45 v1(64.52,16.13)
  BOTTOM w0.13: v1(64.52,16.13) C343.1
N16743015: length 2.6
  TOP w0.13: U26.3 v1(63.34,16.13)
  BOTTOM w0.13: C344.1 63.34,16.86 v1(63.34,16.13)
N16743022: length 2.8
  TOP w0.13: U26.4 62.84,15.52 v1(62.23,16.13)
  BOTTOM w0.13: v1(62.23,16.13) C345.1
N16743029: length 3.4
  TOP w0.13: U26.5 62.34,15.13 61.59,15.88 v1(61.09,15.88)
  BOTTOM w0.13: v1(61.09,15.88) C346.1
N16744367: length 3.5
  TOP w0.254: v1(59.53,11.68) 60.2,11.68 60.46,11.95 U26.9
  TOP w0.508: R230.1 v1(59.53,11.68)
  BOTTOM w0.508: R556.2 v1(59.53,11.68)
N16744371: length 3.6
  TOP w0.254: U26.8 60.45,12.45 60.07,12.83 v1(59.53,12.83)
  TOP w0.508: R229.1 v1(59.53,12.83)
  BOTTOM w0.508: R551.2 v1(59.53,12.83)
N16744375: length 3.9
  TOP w0.254: v1(59.56,13.97) 60.59,12.95 U26.7
  TOP w0.508: R227.1 v1(59.56,13.97)
  BOTTOM w0.508: v1(59.56,13.97) 59.44,13.84 R550.2
N16744379: length 3.8
  TOP w0.254: v1(59.53,10.54) 60.07,10.54 60.98,11.45 U26.10
  TOP w0.508: R235.2 v1(59.53,10.54)
  BOTTOM w0.508: R557.2 v1(59.53,10.54)
N16782266: length 16.5
  TOP w0.254: U11.E23 75.16,73.65 v1(74.87,73.36)
  BOTTOM w0.254: 74.68,77.5 75.16,77.02 75.16,73.65 v1(74.87,73.36)
  BOTTOM w0.508: 74.68,77.5 72.32,79.85 72.32,83.25 71.37,84.2 68.01,84.2 FB9.2
N16818596: length 4.5
  BOTTOM w0.13: R411.1 4.37,80.7 J6.9
N16818719: length 2.5
  BOTTOM w0.13: U43.1 24.22,79.41 R412.1 R417.1
N16819128: length 3.6
  TOP w0.13: v1(24.26,88.27) 25.08,89.09 U7.16
  BOTTOM w0.13: R362.2 23.75,87.25 23.75,87.76 v1(24.26,88.27)
N16839102: length 5.7
  TOP w0.254: C23.1 79.79,95.77 U4.14
  TOP w0.508: v1(81,95.43) 80.14,95.43 C23.1
  BOTTOM w0.508: v1(81,95.43) 79.92,95.43 R338.1
N16839202: length 3.4
  TOP w0.13: U4.13 v1(79.14,97.3)
  BOTTOM w0.13: R322.2 78.5,97.94 v1(79.14,97.3)
N16839209: length 2.3
  TOP w0.13: U4.2 72.01,98.84 72.01,96.77 R34.2
N16839216: length 2.5
  TOP w0.13: 70.74,96.65 71.34,97.25 U4.1
N16844891: length 2.7
  TOP w0.13: D4.2 v1(91.31,107.9)
  BOTTOM w0.13: v1(91.31,107.9) 92.33,108.92 R286.2
N16844892: length 3.2
  TOP w0.13: D9.2 v1(103,106.93)
  BOTTOM w0.13: v1(103,106.93) R281.2
N16844893: length 3.2
  TOP w0.13: D10.2 v1(105.03,106.93)
  BOTTOM w0.13: v1(105.03,106.93) R280.2
N16844894: length 3.2
  TOP w0.13: D7.2 v1(98.81,106.93)
  BOTTOM w0.13: v1(98.81,106.93) R283.2
N16844899: length 3.2
  TOP w0.13: D8.2 v1(100.97,106.93)
  BOTTOM w0.13: v1(100.97,106.93) R282.2
N16844909: length 3.2
  TOP w0.13: D3.2 v1(90.17,106.93)
  BOTTOM w0.13: v1(90.17,106.93) R287.2
N16844924: length 2.9
  TOP w0.13: D6.2 v1(97.79,107.9)
  BOTTOM w0.13: v1(97.79,107.9) 97.79,108.01 R284.2
N16844930: length 2.7
  TOP w0.13: D5.2 v1(93.47,107.9)
  BOTTOM w0.13: R285.2 94.49,108.92 v1(93.47,107.9)
N16880569: length 22.6
  TOP w0.13: U9.1 v1(61.72,79.37) 61.07,80.02 U9.19
  L4_SIG2 w0.13: v1(61.33,87.86) 61.84,87.86 62.3,87.41 62.3,79.95 v1(61.72,79.37)
  BOTTOM w0.13: R416.1 60.96,79.37 v1(61.72,79.37) ; U39.19 61.71,87.51 61.36,87.86 v1(61.33,87.86) 61.32,87.86 61.21,87.76 60.83,87.76 59.94,86.86 U39.1
N16898152: length 1.5
  BOTTOM w0.13: R302.1 R298.2
N16899204: length 1.3
  BOTTOM w0.13: R415.1 R409.2
N16899853: length 1.3
  BOTTOM w0.13: R480.1 R481.2
N16900690: length 1.3
  BOTTOM w0.13: R492.1 R491.2
N17007255: length 34.4
  TOP w0.13: 73.02,92.33 72.29,92.33 v1(72.28,92.31) ; v1(60.2,69.84) 63.57,69.84 R111.1
  L4_SIG2 w0.13: v1(60.2,69.84) 60.2,71.47 60.8,72.07 60.8,72.14 62.29,73.63 62.77,73.63 64.45,75.31 64.45,80.09 64.78,80.42 64.78,82.35 68.33,85.9 68.33,86.56 70.01,88.25 70.01,92.14 70.29,92.42 72.17,92.42 v1(72.28,92.31)
  BOTTOM w0.13: v1(72.28,92.31) U36.4
N17015946: length 4.6
  BOTTOM w0.508: J14.2 5,12.45 ; J14.2 3.39,14.06 ; J14.2 3.39,12.45 ; J14.2 5,14.06
N17047964: length 2.2
  BOTTOM w0.13: U58.2 31.49,28.43 31.75,28.69 31.75,28.96 R515.1
N17047991: length 5.5
  BOTTOM w0.13: U58.22 32.14,20.51 31.88,20.25 30.43,20.25 R541.1 R542.1
N17048274: length 3.7
  BOTTOM w0.13: U58.14 37.34,20.06 37.72,19.68 R544.1
N17048276: length 3.5
  BOTTOM w0.13: R545.1 36.69,18.17 U58.15
N17049952:
  vias: v3(24.77,53.34) v3(24.77,52.07) v3(26.16,52.07) v3(27.49,52.14)
N17050053: length 3.3
  TOP w0.13: R165.1 R166.2 17.48,52.91 U14.5
N17050067: length 1.1
  TOP w0.13: R165.2 R164.1
N17050085:
  vias: v1(24.13,58.29) v1(24.13,57.02)
N17050095: length 7.4
  TOP w0.13: U14.3 20.83,56.21 19.99,55.37 R156.2
N17050109: length 5.2
  TOP w0.13: U14.4 19.56,57.02 19.05,56.52 C69.1
N17050128: length 4.4
  TOP w0.13: 17.4,54.23 20.19,54.23 20.83,53.59 U14.6
N17050161: length 1.1
  TOP w0.13: R159.1 C72.1
N17074741: length 5.4
  BOTTOM w0.13: J6.10 2.54,84.63 R352.1
N17080008: length 2.4
  TOP w0.13: v1(55.73,81.97) U9.16
  BOTTOM w0.13: v1(55.73,81.97) 55.91,81.79 R406.2
N17080011: length 2.8
  TOP w0.13: v1(55.73,81.2) 56.03,80.9 56.39,80.9 56.62,80.67 U9.18
  BOTTOM w0.13: v1(55.73,81.2) 55.97,80.96 56.12,80.96 56.31,80.77 R408.2
N17084990: length 2.5
  TOP w0.13: U1.3 v1(12.53,117.16)
  BOTTOM w0.13: R268.2 13.65,117.16 v1(12.53,117.16)
N17085264: length 4
  TOP w0.13: Q3.G 16.96,110.55 v1(18.03,109.47)
  BOTTOM w0.13: R278.2 R279.1 17.65,109.86 v1(18.03,109.47)
N17085270: length 1.8
  TOP w0.13: R5.1 17.53,113.69 17.87,113.34 Q3.D
N17085272: length 1.7
  TOP w0.13: U2.2 18.32,115.06 18.54,114.83 R5.2
N17085280: length 3.1
  TOP w0.13: Q5.G v1(23.83,111.38)
  BOTTOM w0.13: R274.2 R275.2 23.83,111.3 v1(23.83,111.38)
N17085284: length 3.8
  TOP w0.13: R4.1 24.77,115.57 Q5.D
N17085292: length 3
  TOP w0.13: Q4.G v1(20.49,111.38)
  BOTTOM w0.13: v1(20.49,111.38) 20.49,111.34 R277.2 R276.2
N17085296: length 1.7
  TOP w0.13: R6.2 21.97,114.94 21.82,115.09 U2.4
N17085298: length 1.8
  TOP w0.13: Q4.D 21.43,113.06 20.95,113.54 R6.1
N17085459: length 2.5
  TOP w0.13: R4.2 24.19,117.16 U2.3
N17134629: length 3.8
  BOTTOM w0.203: U29.A1 U29.B1 66.17,106.67 R299.2 66.67,106.18 U29.A1 ; U29.A1 66.66,107.7
N17135096: length 2.7
  BOTTOM w0.203: U29.A2 66.67,108.85 R296.1 66.17,109.09 U29.B2 U29.A2
N17135910: length 1.2
  BOTTOM w0.13: R296.2 65.67,108.83 U29.C2
N17144335: length 6.2
  TOP w0.13: R152.1 37.08,59.44 36.2,60.32 v1(36.2,61.34)
  BOTTOM w0.13: U46.3 36.7,63.37 36.2,62.86 v1(36.2,61.34)
N17156111: length 10.1
  BOTTOM w0.13: Y2.2 21.72,106.28 C129.2 R307.2 23.45,102.28 U33.1
N17156113: length 6.3
  BOTTOM w0.13: Y2.1 20.7,106.03 C130.2 20.7,104.01 19.94,103.25 19.05,103.25
N17156222: length 1.9
  BOTTOM w0.13: R308.1 19.09,102.28 U33.14
N17156522: length 2.2
  BOTTOM w0.13: R311.1 19.81,100.33 U33.11
N17156525: length 2.3
  BOTTOM w0.13: U33.9 19.97,99.03 R312.1
N17156528: length 1.9
  BOTTOM w0.13: U33.8 19.09,98.38 R323.1
N17156983: length 2.3
  TOP w0.13: R22.1 v1(22.23,101.35)
  BOTTOM w0.13: v1(22.23,101.35) 21.86,100.98 U33.12
N17156986: length 2.5
  TOP w0.13: v1(22.23,102.11) 22.48,102.36 R21.1
  BOTTOM w0.13: v1(22.23,102.11) 21.75,101.63 U33.13
N17183635: length 118
  TOP w0.13: v1(38.99,37.46) 38.99,36.83 38.84,36.68 U23.27
  L4_SIG2 w0.13: v1(38.99,37.46) 39.5,36.96 40.64,36.96 41.66,37.97 42,37.97 45.44,41.42 45.44,44.84 44.99,45.28 44.99,50.8 46.72,52.52 46.72,54.92 47.34,55.54 47.34,57.84 51.67,62.17 54.52,62.17 57.21,64.86 58.27,64.86 61.03,67.62 61.03,68.5 63.34,70.8 63.34,72.45 66.59,75.7 66.59,77.51 67.64,78.55 67.64,82.08 69.58,84.03 69.84,84.03 70.53,84.72 70.53,85.47 74.7,89.64 76.65,89.64 77.58,90.58 78.11,90.58 82.05,94.52 v1(82.05,94.61) ; v1(93.22,100.84) 94.23,99.82 94.23,96.77 99.81,91.2 99.81,90.14 100.18,89.77 101.34,89.77 103.38,87.73 v1(103.38,86.36)
  BOTTOM w0.13: v1(82.05,94.61) 85.34,94.61 91.57,100.84 v1(93.22,100.84) ; R364.2 v1(103.38,86.36)
N17183685: length 81.5
  TOP w0.13: R70.2 77.72,88.15 77.44,88.43 77.44,90.58 v1(76.83,91.19) ; v1(40.14,37.46) U23.25
  L4_SIG2 w0.13: v1(40.14,37.46) 40.64,37.46 41.53,38.35 41.94,38.35 45.13,41.54 45.13,44.71 44.69,45.16 44.69,50.93 46.35,52.59 46.35,55.33 46.04,55.64 46.04,58.66 49.1,61.72 50.79,61.72 51.54,62.48 54.39,62.48 57.08,65.17 58.14,65.17 60.72,67.75 60.72,68.63 62.1,70 62.1,72.13 62.67,72.7 63.15,72.7 66.28,75.83 66.28,78.78 67.33,79.83 67.33,82.21 69.46,84.34 69.71,84.34 70.22,84.85 70.22,85.6 75.35,90.73 76.38,90.73 v1(76.83,91.19)
N17184172: length 226
  TOP w0.13: U23.16 45.99,35.92 45.72,36.2 v1(45.72,36.32) ; v1(91.69,87.38) R80.2 R81.2
  L3_SIG1 w0.13: v1(31.24,48.51) 31.17,48.59 31.17,51.38 24.91,57.64 24.91,60.43 22.83,62.51 20.81,62.51 18.23,65.09 18.23,69.78 12.89,75.12 12.89,77.28 11.68,78.49 11.68,81.53 12.45,82.3 12.45,85.34 10.92,86.87 10.92,96.52 12.45,98.04 12.45,100.2 11.25,101.4 8.45,101.4 5.97,103.89 5.97,108.33 6.86,109.22 8.7,109.22 13.21,113.73 19.24,113.73 21.56,111.41 21.56,106.16 23.26,104.46 25.68,104.46 28.87,107.65 41.88,107.65 45.07,104.46 57.35,104.46 60.66,107.77 63.44,107.77 65.04,109.36 79.74,109.36 80.77,108.33 80.77,107.81 80.53,107.56 80.53,106.95 81.46,106.02 v1(81.46,105.66)
  L4_SIG2 w0.13: v1(45.72,36.32) 45.72,34.8 44.85,33.93 36.74,33.93 29.46,41.2 29.46,47.24 30.73,48.51 v1(31.24,48.51) ; v1(81.46,105.66) 81.66,105.46 81.66,97.1 83.13,95.63 86.74,95.63 88.14,94.23 89.79,94.23 91.69,92.33 v1(91.69,87.38)
N17197007: length 3.3
  TOP w0.13: J7.10 v1(128.4,79.5)
  BOTTOM w0.13: R414.2 v1(128.4,79.5)
N17197255: length 13.2
  TOP w0.13: U8.2 124.33,83.82 v1(125.6,82.55)
  BOTTOM w0.13: R426.1 C186.1 R414.1 128.4,81.91 126.24,81.91 v1(125.6,82.55)
N17205778: length 3
  TOP w0.13: v1(50.16,35.05) C89.1 49.35,35 U22.5
  BOTTOM w0.13: C89.1 v1(50.16,35.05)
N17205782: length 4.9
  TOP w0.13: v1(48.64,31.19) U22.1 49.28,31.12 R207.2
  BOTTOM w0.13: C310.2 R510.1 49.3,31.75 48.74,31.19 v1(48.64,31.19)
N17205788: length 5.4
  TOP w0.13: R197.1 51.23,35 U22.4 51.99,33.58 v1(52.07,33.66)
  BOTTOM w0.13: R510.2 C310.1 v1(52.07,33.66)
N17205791: length 5.4
  TOP w0.13: v1(53.21,31.24) C91.1 R209.1 R208.1 51.23,29.92 U22.3
  BOTTOM w0.13: C91.1 v1(53.21,31.24)
N17205925: length 21.5
  TOP w0.13: v1(86,67.5) 86.33,67.16 U11.AB13 ; R104.2 R109.2 103.73,69.44 101.93,69.44 v1(101.47,68.99)
  L3_SIG1 w0.13: v1(101.47,68.99) 101.24,69.22 99.64,69.22 97.99,67.56 89.64,67.56 89.15,67.08 86.42,67.08 v1(86,67.5)
N17205949: length 18.2
  TOP w0.13: v1(86.03,66.05) 86.03,66.16 U11.AA12
  L3_SIG1 w0.13: v1(100.74,64.69) 100.38,64.69 100.2,64.52 87.12,64.52 86.03,65.61 v1(86.03,66.05)
  BOTTOM w0.13: R450.2 R454.2 101.09,64.9 100.89,64.69 v1(100.74,64.69)
N17209063: length 3
  TOP w0.13: U19.5 61.98,33.93 C92.1 R204.1
N17209071: length 4.6
  TOP w0.13: U19.1 62.69,36.37 v1(62.74,36.32)
  BOTTOM w0.13: R502.1 C298.2 R501.2 ; R501.2 62.61,36.45 v1(62.74,36.32) ; R501.2 R497.2
N17209083: length 5.7
  TOP w0.13: R203.1 59.69,32.64 v1(60.15,33.1) U19.4
  BOTTOM w0.13: C298.1 R502.2 60.45,34.92 60.45,33.4 v1(60.15,33.1)
N17209089: length 4.8
  TOP w0.13: U19.3 58.98,36.37 R196.1 ; R195.1 R196.1 ; R196.1 C85.1 R191.2
N17209568: length 3
  TOP w0.13: R201.1 C90.1 29.46,34.32 U18.5
N17209576: length 6.5
  TOP w0.13: R188.2 R189.2 29.59,36.83 U18.1 v1(30.35,36.75)
  BOTTOM w0.13: R506.1 C305.2 30.35,35.56 v1(30.35,36.75)
N17209588: length 4.3
  TOP w0.13: U18.4 v1(27.64,33.48) 27.18,33.02 R200.1
  BOTTOM w0.13: C305.1 R506.2 28.07,33.91 v1(27.64,33.48)
N17209594: length 4.6
  TOP w0.13: U18.3 26.85,36.75 R194.1 ; R194.1 C86.1 ; R194.1 R193.1 R192.2
N17210087: length 3
  TOP w0.13: U24.5 61.98,24.66 C101.1 R223.1
N17210095: length 5.3
  TOP w0.13: U24.1 62.03,27.99 v1(62.1,28.07)
  BOTTOM w0.13: R523.2 R524.2 C331.2 ; C331.2 61.47,27.43 v1(62.1,28.07) ; C331.2 R525.1
N17210107: length 6.3
  TOP w0.13: R222.1 59.16,23.39 v1(59.16,23.95) 59.92,24.71 U24.4
  BOTTOM w0.13: C331.1 R525.2 60.45,25.78 59.16,24.49 v1(59.16,23.95)
N17210113: length 4.8
  TOP w0.13: R211.1 R212.2 ; R212.2 58.98,27.1 U24.3 ; R212.2 C93.1 R210.1
N17340888: length 13.1
  TOP w0.13: U11.D20 75.09,72.15 v1(75.09,72.25)
  BOTTOM w0.13: TP21.1 66.43,76.44 66.43,75.43 69.82,72.04 74.21,72.04 74.36,71.89 74.73,71.89 v1(75.09,72.25)
N17722224: length 4.7
  TOP w0.254: D2.2 65.53,108.97 R20.1
N17757813: length 3.5
  TOP w0.13: v1(127.07,68.07) 127.25,67.89 R133.1
  BOTTOM w0.13: U45.4 v1(127.07,68.07)
N17757815: length 9.5
  TOP w0.13: v1(122.55,72.39) 122.56,72.39 R120.1
  BOTTOM w0.13: v1(122.55,72.39) 123.57,71.37 123.57,71.07 126.42,68.22 U45.5
N17758292: length 31.4
  TOP w0.13: R119.1 v1(121.54,72.64)
  L4_SIG2 w0.13: v1(121.54,72.64) 123.88,70.31 125.22,70.31 126.36,69.16 126.36,63.75 125.67,63.05 125.67,62.58 129.34,58.91 129.34,51 v1(129.92,50.42)
  BOTTOM w0.13: v1(129.92,50.42) 130.23,50.42 130.28,50.36 U49.7
N17758583: length 2.9
  BOTTOM w0.13: R376.2 128.52,84.58 128.96,84.15 U41.7
N17758585: length 2.9
  BOTTOM w0.13: R381.2 127.83,83.89 128.63,83.89 128.77,83.75 U41.6
N17814979: length 2.7
  BOTTOM w0.508: R500.1 C293.1 55.79,37.8 U56.1
N17839489: length 6.8
  TOP w0.13: U23.24 40.79,36.25 v1(40.61,36.42) ; R187.2 v1(43.56,37.59)
  L4_SIG2 w0.13: v1(43.56,37.59) 41.91,35.94 41.1,35.94 v1(40.61,36.42)
N17852592: length 52
  TOP w0.13: v1(56.8,66.01) 56.81,66 62.76,66 62.86,65.91 63.63,65.91 R132.2 ; U23.23 41.44,36.59 41.15,36.88 41.15,37.85 v1(39.75,39.24)
  L4_SIG2 w0.13: v1(56.8,66.01) 50.56,66.01 50.08,65.52 49.57,65.52 44.39,60.34 44.39,55.66 43.71,54.98 43.71,45.27 44.52,44.46 44.52,41.8 43.83,41.11 43.02,41.11 41.85,39.94 40.45,39.94 v1(39.75,39.24)
N17852603: length 45
  TOP w0.13: v1(41.91,36.7) 41.91,36.07 42.09,35.89 U23.22 ; v1(57.4,64.39) 57.4,64.57 57.86,65.02 62.99,65.02 R138.2
  L4_SIG2 w0.13: v1(57.4,64.39) 54.87,61.86 51.79,61.86 47.64,57.71 47.64,55.41 47.03,54.8 47.03,49.92 47.06,49.89 47.06,49.42 45.86,48.23 45.86,40.75 41.91,36.8 v1(41.91,36.7)
N17863265: length 4.3
  BOTTOM w0.13: R310.1 4.32,97.93 J6.11
N17863276: length 5
  BOTTOM w0.13: R348.1 2.54,97.68 J6.12
N17942790: length 6
  TOP w0.13: U11.P21 81.29,72.35 v1(81.55,72.61)
  BOTTOM w0.13: v1(81.55,72.61) 81.41,72.61 80.77,73.25 TP20.1
N17944182: length 15.9
  TOP w0.13: U11.AD5 87.94,62.26 94.43,62.26 96.75,59.94 R149.1 100.71,59.7 C66.1
N18003575: length 6
  TOP w0.13: J16.20 110.28,4.77 110.28,8.34 R256.2 R257.2
N18051330: length 21.9
  TOP w0.13: v1(80.01,71.68) 80.46,71.68 U11.N20 ; v1(85.47,88.93) 85.45,88.9 R62.1
  L3_SIG1 w0.13: v1(80.01,71.68) 80.23,71.89 80.47,71.89 80.88,72.29 80.88,76.25 83.26,78.63 83.46,78.63 84.73,79.91 84.73,80.21 85.22,80.7 85.22,82.65 84.18,83.69 84.18,87.63 v1(85.47,88.93)
N18051447: length 15.6
  TOP w0.13: U11.N25 80.48,75.15 81.18,75.84 81.18,80.85 81.91,81.58 81.91,82.55 82.8,83.44 82.8,85.6 82.46,85.94 82.46,87.67 R61.1
N18051467: length 18.6
  TOP w0.13: v1(81.91,86.11) 82.14,86.33 82.14,87.78 82.68,88.32 R60.1 ; U11.P22 81.19,73.05 81.92,73.05 v1(81.94,73.02)
  BOTTOM w0.13: v1(81.91,86.11) 81.91,85.22 81.53,84.84 81.53,83.06 80.88,82.41 80.88,80.8 81.65,80.03 81.65,76.47 81.14,75.95 81.14,73.31 81.42,73.03 81.73,73.03 81.74,73.02 v1(81.94,73.02)
N18074781: length 43.1
  TOP w0.13: v1(85.35,69.45) 85.68,69.11 U11.AA16 ; R64.2 v2(110.49,88.65)
  L3_SIG1 w0.13: v1(85.35,69.45) 85.77,69.03 87.03,69.03 89.12,71.12 94.14,71.12 95.25,72.23 98.83,72.23 99.24,72.64 103,72.64 104.54,74.19 104.54,79.52 v2(105.28,80.26)
  L4_SIG2 w0.13: v2(105.28,80.26) 104.9,80.64 104.9,81.86 107,83.96 110.83,83.96 111.52,84.65 111.52,86.42 111.12,86.82 111.12,88.01 v2(110.49,88.65)
N18074818: length 67.6
  TOP w0.13: U11.AE16 93.66,69.1 95.29,70.72 95.67,70.72 96.83,71.88 100.33,71.88 101.16,71.05 101.76,71.05 104.57,73.87 104.57,80.95 105.72,82.1 110.38,82.1 111.26,82.98 v1(115.44,82.98)
  L4_SIG2 w0.13: J2.1 115.44,109.19 113.09,106.84 113.09,106.32 113.72,105.69 113.72,99.94 113.45,99.67 113.45,95.33 114.67,94.1 114.67,92.29 115.89,91.08 115.89,86.25 116.11,86.02 116.11,83.65 v1(115.44,82.98)
N18074820: length 75
  TOP w0.13: U11.AD16 87.94,68.79 93.79,68.79 95.41,70.41 95.8,70.41 96.96,71.57 100.13,71.57 100.96,70.75 101.89,70.75 104.9,73.76 104.9,77.83 105.99,78.92 105.99,80.55 106.51,81.07 109.94,81.07 111,82.13 117.01,82.13 117.4,81.75 121.52,81.75 v1(121.97,82.19)
  L4_SIG2 w0.13: v1(121.97,82.19) 117.35,86.82 117.35,93.6 116.64,94.31 116.64,108.57 117.98,109.92 J2.2
N18075381: length 93.7
  TOP w0.13: v1(97.89,73.1) 97.89,75.95 99.28,77.34 101.98,77.34 103.49,78.86 103.49,80.75 105.3,82.55 106.32,82.55 107.73,83.96 112.96,83.96 113.13,83.78 115.41,83.78 116.01,84.38 116.05,84.38 117.4,85.72 121.95,85.72 122.55,85.12 124.46,85.12 124.94,85.6 126.9,85.6 127.97,86.66 130.99,86.66 v1(132.46,88.14) ; U11.AC18 v1(86.99,69.93)
  L3_SIG1 w0.13: v1(132.46,88.14) 131.71,87.39 131.71,77.24 132.97,75.98 132.97,74.17 135.69,71.45 135.69,61.5 132.84,58.65 v1(132.84,56.52) ; v1(86.99,69.93) 88.94,71.88 94.03,71.88 95.22,73.08 97.87,73.08 v1(97.89,73.1)
  BOTTOM w0.13: v1(132.84,56.52) 132.84,55.88 133.1,55.63 R478.2
N18075410: length 7.4
  TOP w0.13: SW1.1 v1(134.11,55.4) SW1.2
  BOTTOM w0.13: R477.1 v1(134.11,55.4) R472.1
N18075448: length 2.6
  BOTTOM w0.13: R478.1 R477.2 C262.1
N18075562: length 9.4
  TOP w0.13: v1(76,76.37) 76,75.85 75.29,75.14 U11.E25
  BOTTOM w0.13: R388.1 73.28,80.01 75.51,77.77 75.51,76.85 v1(76,76.37)
N18075603: length 13.3
  TOP w0.13: U11.P20 v1(81.63,71.7)
  BOTTOM w0.13: R383.1 84.33,82.04 83.57,81.28 83.57,80.49 82.76,79.68 82.76,73.62 82.64,73.5 82.64,72.09 82.24,71.7 v1(81.63,71.7)
